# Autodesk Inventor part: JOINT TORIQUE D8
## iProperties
Created: 2004-11
Part Number: JOINT TORIQUE D8
Document SubType Name: Modeling
Designer: Bruno
Manufacturer: Standard
Standards Organization: Custom
Author: Bruno
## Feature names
1. Base1
